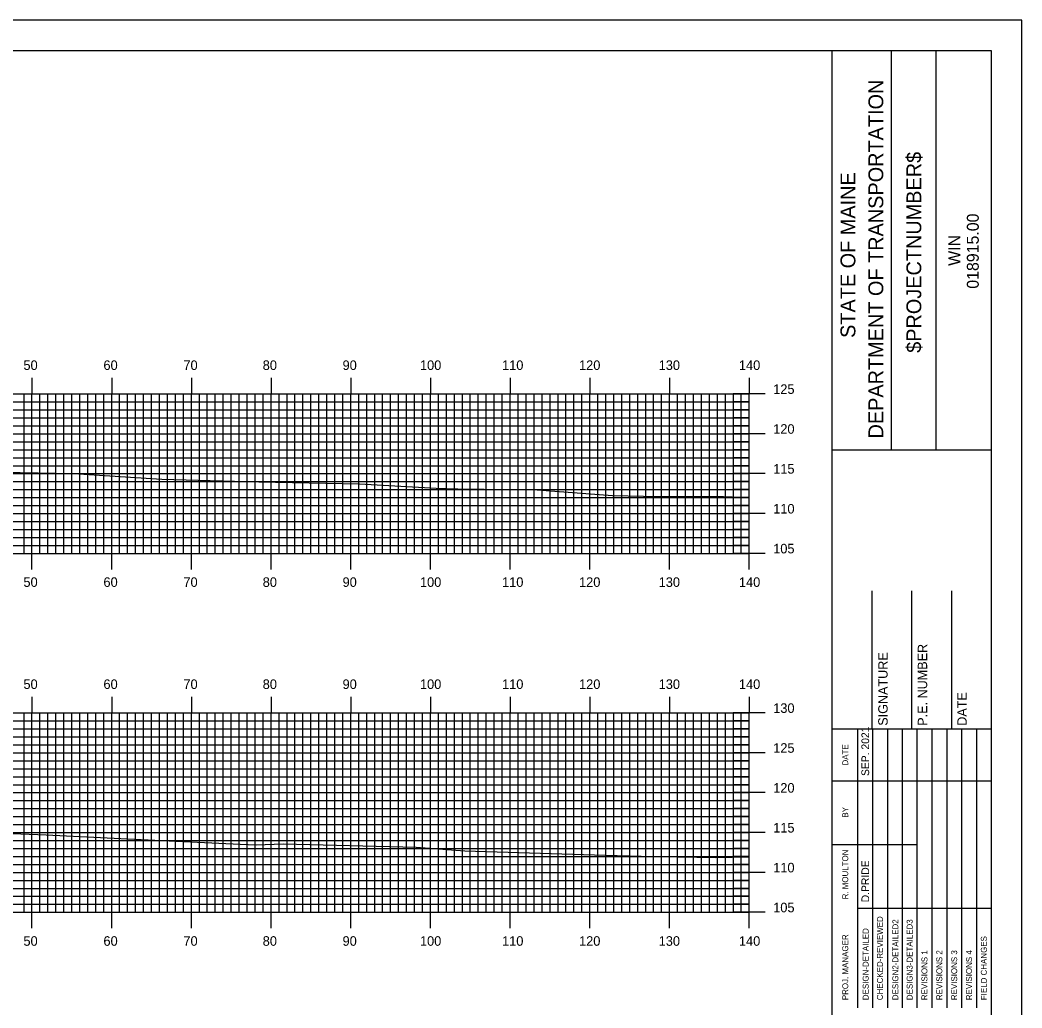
# Model space of a CAD drawing. Extents: x 1780286 to 1780629, y 442591 to 442811.
# Drawn here: x 1780500.4 to 1780626.1, y 442686.7 to 442810.5 of the extents above; entities that cross this region are included whole.
import ezdxf

# ---------------------------------------------------------------- set-up
doc = ezdxf.new("R2010")
doc.units = 0
for name, color, linetype in [('BORDER', 7, 'Continuous'), ('H_V ANNOTATION', 7, 'Continuous'), ('MAJOR', 7, 'Continuous'), ('MINOR', 7, 'Continuous'), ('PLOT BOUNDARY', 7, 'Continuous'), ('S_Roadway_Centerline', 7, 'Continuous')]:
    doc.layers.add(name, color=color, linetype=linetype)

msp = doc.modelspace()

# ---------------------------------------------------------------- linework, layer by layer
at = {"layer": 'BORDER'}
for p, q in [((1780602.27, 442596.67), (1780602.27, 442806.67)), ((1780609.73, 442756.66), (1780609.73, 442806.66)), ((1780615.32, 442756.66), (1780615.32, 442806.66)), ((1780602.27, 442756.65), (1780622.27, 442756.65)), ((1780607.27, 442721.67), (1780607.27, 442738.97)), ((1780612.27, 442721.67), (1780612.27, 442738.97)), ((1780617.27, 442721.67), (1780617.27, 442738.97)), ((1780602.27, 442721.67), (1780622.27, 442721.67))]:
    msp.add_line(p, q, dxfattribs=at)
msp.add_lwpolyline([(1780302.27, 442596.67), (1780622.27, 442596.67), (1780622.27, 442806.67), (1780302.27, 442806.67)], close=True, dxfattribs=at)
for points in [[(1780605.5, 442715.17), (1780605.5, 442721.67)], [(1780607.36, 442686.68), (1780607.36, 442721.67)], [(1780609.23, 442721.67), (1780609.23, 442686.68)], [(1780611.09, 442686.68), (1780611.09, 442721.67)], [(1780612.95, 442686.68), (1780612.95, 442721.67)], [(1780614.82, 442686.68), (1780614.82, 442721.67)], [(1780616.68, 442686.68), (1780616.68, 442721.67)], [(1780618.54, 442686.68), (1780618.54, 442721.67)], [(1780620.41, 442686.68), (1780620.41, 442721.67)], [(1780605.5, 442686.68), (1780605.5, 442720.26)], [(1780602.27, 442715.17), (1780622.27, 442715.17)], [(1780602.27, 442707.17), (1780605.5, 442707.17)], [(1780605.5, 442707.17), (1780612.95, 442707.17)], [(1780605.5, 442699.17), (1780622.27, 442699.17)]]:
    msp.add_lwpolyline(points, dxfattribs=at)
at = {"layer": 'MAJOR'}
for p, q in [((1780501.87, 442765.67), (1780501.87, 442763.67)), ((1780511.87, 442765.67), (1780511.87, 442763.67)), ((1780521.87, 442765.67), (1780521.87, 442763.67)), ((1780531.87, 442765.67), (1780531.87, 442763.67)), ((1780541.87, 442765.67), (1780541.87, 442763.67)), ((1780551.87, 442765.67), (1780551.87, 442763.67)), ((1780561.87, 442765.67), (1780561.87, 442763.67)), ((1780571.87, 442765.67), (1780571.87, 442763.67)), ((1780581.87, 442765.67), (1780581.87, 442763.67)), ((1780591.87, 442765.67), (1780591.87, 442763.67)), ((1780311.87, 442763.67), (1780591.87, 442763.67)), ((1780311.87, 442763.67), (1780591.87, 442763.67)), ((1780501.87, 442743.67), (1780501.87, 442763.67)), ((1780511.87, 442743.67), (1780511.87, 442763.67)), ((1780521.87, 442743.67), (1780521.87, 442763.67)), ((1780531.87, 442743.67), (1780531.87, 442763.67)), ((1780541.87, 442743.67), (1780541.87, 442763.67)), ((1780551.87, 442743.67), (1780551.87, 442763.67)), ((1780561.87, 442743.67), (1780561.87, 442763.67)), ((1780571.87, 442743.67), (1780571.87, 442763.67)), ((1780581.87, 442743.67), (1780581.87, 442763.67)), ((1780593.87, 442763.67), (1780589.86, 442763.67)), ((1780591.87, 442743.67), (1780591.87, 442763.67)), ((1780591.87, 442743.67), (1780591.87, 442763.67)), ((1780311.87, 442758.67), (1780591.87, 442758.67)), ((1780593.87, 442758.67), (1780589.86, 442758.67)), ((1780311.87, 442753.67), (1780591.87, 442753.67)), ((1780593.87, 442753.67), (1780589.86, 442753.67)), ((1780311.87, 442748.67), (1780591.87, 442748.67)), ((1780593.87, 442748.67), (1780589.86, 442748.67)), ((1780311.87, 442743.67), (1780591.87, 442743.67)), ((1780311.87, 442743.67), (1780591.87, 442743.67)), ((1780501.87, 442741.66), (1780501.87, 442743.67)), ((1780511.87, 442741.66), (1780511.87, 442743.67)), ((1780521.87, 442741.66), (1780521.87, 442743.67)), ((1780531.87, 442741.66), (1780531.87, 442743.67)), ((1780541.87, 442741.66), (1780541.87, 442743.67)), ((1780551.87, 442741.66), (1780551.87, 442743.67)), ((1780561.87, 442741.66), (1780561.87, 442743.67)), ((1780571.87, 442741.66), (1780571.87, 442743.67)), ((1780581.87, 442741.66), (1780581.87, 442743.67)), ((1780593.87, 442743.67), (1780589.86, 442743.67)), ((1780591.87, 442741.66), (1780591.87, 442743.67)), ((1780501.87, 442725.67), (1780501.87, 442723.67)), ((1780511.87, 442725.67), (1780511.87, 442723.67)), ((1780521.87, 442725.67), (1780521.87, 442723.67)), ((1780531.87, 442725.67), (1780531.87, 442723.67)), ((1780541.87, 442725.67), (1780541.87, 442723.67)), ((1780551.87, 442725.67), (1780551.87, 442723.67)), ((1780561.87, 442725.67), (1780561.87, 442723.67)), ((1780571.87, 442725.67), (1780571.87, 442723.67)), ((1780581.87, 442725.67), (1780581.87, 442723.67)), ((1780591.87, 442725.67), (1780591.87, 442723.67)), ((1780311.87, 442723.67), (1780591.87, 442723.67)), ((1780311.87, 442723.67), (1780591.87, 442723.67)), ((1780501.87, 442698.67), (1780501.87, 442723.67)), ((1780511.87, 442698.67), (1780511.87, 442723.67)), ((1780521.87, 442698.67), (1780521.87, 442723.67)), ((1780531.87, 442698.67), (1780531.87, 442723.67)), ((1780541.87, 442698.67), (1780541.87, 442723.67)), ((1780551.87, 442698.67), (1780551.87, 442723.67)), ((1780561.87, 442698.67), (1780561.87, 442723.67)), ((1780571.87, 442698.67), (1780571.87, 442723.67)), ((1780581.87, 442698.67), (1780581.87, 442723.67)), ((1780593.87, 442723.67), (1780589.86, 442723.67)), ((1780591.87, 442698.67), (1780591.87, 442723.67)), ((1780591.87, 442698.67), (1780591.87, 442723.67)), ((1780311.87, 442718.67), (1780591.87, 442718.67)), ((1780593.87, 442718.67), (1780589.86, 442718.67)), ((1780311.87, 442713.67), (1780591.87, 442713.67)), ((1780593.87, 442713.67), (1780589.86, 442713.67)), ((1780311.87, 442708.67), (1780591.87, 442708.67)), ((1780593.87, 442708.67), (1780589.86, 442708.67)), ((1780311.87, 442703.67), (1780591.87, 442703.67)), ((1780593.87, 442703.67), (1780589.86, 442703.67)), ((1780311.87, 442698.67), (1780591.87, 442698.67)), ((1780311.87, 442698.67), (1780591.87, 442698.67)), ((1780501.87, 442696.66), (1780501.87, 442698.67)), ((1780511.87, 442696.66), (1780511.87, 442698.67)), ((1780521.87, 442696.66), (1780521.87, 442698.67)), ((1780531.87, 442696.66), (1780531.87, 442698.67)), ((1780541.87, 442696.66), (1780541.87, 442698.67)), ((1780551.87, 442696.66), (1780551.87, 442698.67)), ((1780561.87, 442696.66), (1780561.87, 442698.67)), ((1780571.87, 442696.66), (1780571.87, 442698.67)), ((1780581.87, 442696.66), (1780581.87, 442698.67)), ((1780593.87, 442698.67), (1780589.86, 442698.67)), ((1780591.87, 442696.66), (1780591.87, 442698.67))]:
    msp.add_line(p, q, dxfattribs=at)
at = {"layer": 'MINOR'}
for p, q in [((1780500.87, 442743.67), (1780500.87, 442763.67)), ((1780502.87, 442743.67), (1780502.87, 442763.67)), ((1780503.87, 442743.67), (1780503.87, 442763.67)), ((1780504.87, 442743.67), (1780504.87, 442763.67)), ((1780505.87, 442743.67), (1780505.87, 442763.67)), ((1780506.87, 442743.67), (1780506.87, 442763.67)), ((1780507.87, 442743.67), (1780507.87, 442763.67)), ((1780508.87, 442743.67), (1780508.87, 442763.67)), ((1780509.87, 442743.67), (1780509.87, 442763.67)), ((1780510.87, 442743.67), (1780510.87, 442763.67)), ((1780512.87, 442743.67), (1780512.87, 442763.67)), ((1780513.87, 442743.67), (1780513.87, 442763.67)), ((1780514.87, 442743.67), (1780514.87, 442763.67)), ((1780515.87, 442743.67), (1780515.87, 442763.67)), ((1780516.87, 442743.67), (1780516.87, 442763.67)), ((1780517.87, 442743.67), (1780517.87, 442763.67)), ((1780518.87, 442743.67), (1780518.87, 442763.67)), ((1780519.87, 442743.67), (1780519.87, 442763.67)), ((1780520.87, 442743.67), (1780520.87, 442763.67)), ((1780522.87, 442743.67), (1780522.87, 442763.67)), ((1780523.87, 442743.67), (1780523.87, 442763.67)), ((1780524.87, 442743.67), (1780524.87, 442763.67)), ((1780525.87, 442743.67), (1780525.87, 442763.67)), ((1780526.87, 442743.67), (1780526.87, 442763.67)), ((1780527.87, 442743.67), (1780527.87, 442763.67)), ((1780528.87, 442743.67), (1780528.87, 442763.67)), ((1780529.87, 442743.67), (1780529.87, 442763.67)), ((1780530.87, 442743.67), (1780530.87, 442763.67)), ((1780532.87, 442743.67), (1780532.87, 442763.67)), ((1780533.87, 442743.67), (1780533.87, 442763.67)), ((1780534.87, 442743.67), (1780534.87, 442763.67)), ((1780535.87, 442743.67), (1780535.87, 442763.67)), ((1780536.87, 442743.67), (1780536.87, 442763.67)), ((1780537.87, 442743.67), (1780537.87, 442763.67)), ((1780538.87, 442743.67), (1780538.87, 442763.67)), ((1780539.87, 442743.67), (1780539.87, 442763.67)), ((1780540.87, 442743.67), (1780540.87, 442763.67)), ((1780542.87, 442743.67), (1780542.87, 442763.67)), ((1780543.87, 442743.67), (1780543.87, 442763.67)), ((1780544.87, 442743.67), (1780544.87, 442763.67)), ((1780545.87, 442743.67), (1780545.87, 442763.67)), ((1780546.87, 442743.67), (1780546.87, 442763.67)), ((1780547.87, 442743.67), (1780547.87, 442763.67)), ((1780548.87, 442743.67), (1780548.87, 442763.67)), ((1780549.87, 442743.67), (1780549.87, 442763.67)), ((1780550.87, 442743.67), (1780550.87, 442763.67)), ((1780552.87, 442743.67), (1780552.87, 442763.67)), ((1780553.87, 442743.67), (1780553.87, 442763.67)), ((1780554.87, 442743.67), (1780554.87, 442763.67)), ((1780555.87, 442743.67), (1780555.87, 442763.67)), ((1780556.87, 442743.67), (1780556.87, 442763.67)), ((1780557.87, 442743.67), (1780557.87, 442763.67)), ((1780558.87, 442743.67), (1780558.87, 442763.67)), ((1780559.87, 442743.67), (1780559.87, 442763.67)), ((1780560.87, 442743.67), (1780560.87, 442763.67)), ((1780562.87, 442743.67), (1780562.87, 442763.67)), ((1780563.87, 442743.67), (1780563.87, 442763.67)), ((1780564.87, 442743.67), (1780564.87, 442763.67)), ((1780565.87, 442743.67), (1780565.87, 442763.67)), ((1780566.87, 442743.67), (1780566.87, 442763.67)), ((1780567.87, 442743.67), (1780567.87, 442763.67)), ((1780568.87, 442743.67), (1780568.87, 442763.67)), ((1780569.87, 442743.67), (1780569.87, 442763.67)), ((1780570.87, 442743.67), (1780570.87, 442763.67)), ((1780572.87, 442743.67), (1780572.87, 442763.67)), ((1780573.87, 442743.67), (1780573.87, 442763.67)), ((1780574.87, 442743.67), (1780574.87, 442763.67)), ((1780575.87, 442743.67), (1780575.87, 442763.67)), ((1780576.87, 442743.67), (1780576.87, 442763.67)), ((1780577.87, 442743.67), (1780577.87, 442763.67)), ((1780578.87, 442743.67), (1780578.87, 442763.67)), ((1780579.87, 442743.67), (1780579.87, 442763.67)), ((1780580.87, 442743.67), (1780580.87, 442763.67)), ((1780582.87, 442743.67), (1780582.87, 442763.67)), ((1780583.87, 442743.67), (1780583.87, 442763.67)), ((1780584.87, 442743.67), (1780584.87, 442763.67)), ((1780585.87, 442743.67), (1780585.87, 442763.67)), ((1780586.87, 442743.67), (1780586.87, 442763.67)), ((1780587.87, 442743.67), (1780587.87, 442763.67)), ((1780588.87, 442743.67), (1780588.87, 442763.67)), ((1780589.87, 442743.67), (1780589.87, 442763.67)), ((1780590.87, 442743.67), (1780590.87, 442763.67)), ((1780311.87, 442762.67), (1780591.87, 442762.67)), ((1780311.87, 442761.67), (1780591.87, 442761.67)), ((1780591.87, 442762.67), (1780589.86, 442762.67)), ((1780591.87, 442761.67), (1780589.86, 442761.67)), ((1780311.87, 442760.67), (1780591.87, 442760.67)), ((1780591.87, 442760.67), (1780589.86, 442760.67)), ((1780311.87, 442759.67), (1780591.87, 442759.67)), ((1780591.87, 442759.67), (1780589.86, 442759.67)), ((1780311.87, 442757.67), (1780591.87, 442757.67)), ((1780311.87, 442756.67), (1780591.87, 442756.67)), ((1780591.87, 442757.67), (1780589.86, 442757.67)), ((1780591.87, 442756.67), (1780589.86, 442756.67)), ((1780311.87, 442755.67), (1780591.87, 442755.67)), ((1780591.87, 442755.67), (1780589.86, 442755.67)), ((1780311.87, 442754.67), (1780591.87, 442754.67)), ((1780591.87, 442754.67), (1780589.86, 442754.67)), ((1780311.87, 442752.67), (1780591.87, 442752.67)), ((1780591.87, 442752.67), (1780589.86, 442752.67)), ((1780311.87, 442751.67), (1780591.87, 442751.67)), ((1780591.87, 442751.67), (1780589.86, 442751.67)), ((1780311.87, 442750.67), (1780591.87, 442750.67)), ((1780591.87, 442750.67), (1780589.86, 442750.67)), ((1780311.87, 442749.67), (1780591.87, 442749.67)), ((1780591.87, 442749.67), (1780589.86, 442749.67)), ((1780311.87, 442747.67), (1780591.87, 442747.67)), ((1780591.87, 442747.67), (1780589.86, 442747.67)), ((1780311.87, 442746.67), (1780591.87, 442746.67)), ((1780591.87, 442746.67), (1780589.86, 442746.67)), ((1780311.87, 442745.67), (1780591.87, 442745.67)), ((1780591.87, 442745.67), (1780589.86, 442745.67)), ((1780311.87, 442744.67), (1780591.87, 442744.67)), ((1780591.87, 442744.67), (1780589.86, 442744.67)), ((1780311.87, 442722.67), (1780591.87, 442722.67)), ((1780500.87, 442698.67), (1780500.87, 442723.67)), ((1780502.87, 442698.67), (1780502.87, 442723.67)), ((1780503.87, 442698.67), (1780503.87, 442723.67)), ((1780504.87, 442698.67), (1780504.87, 442723.67)), ((1780505.87, 442698.67), (1780505.87, 442723.67)), ((1780506.87, 442698.67), (1780506.87, 442723.67)), ((1780507.87, 442698.67), (1780507.87, 442723.67)), ((1780508.87, 442698.67), (1780508.87, 442723.67)), ((1780509.87, 442698.67), (1780509.87, 442723.67)), ((1780510.87, 442698.67), (1780510.87, 442723.67)), ((1780512.87, 442698.67), (1780512.87, 442723.67)), ((1780513.87, 442698.67), (1780513.87, 442723.67)), ((1780514.87, 442698.67), (1780514.87, 442723.67)), ((1780515.87, 442698.67), (1780515.87, 442723.67)), ((1780516.87, 442698.67), (1780516.87, 442723.67)), ((1780517.87, 442698.67), (1780517.87, 442723.67)), ((1780518.87, 442698.67), (1780518.87, 442723.67)), ((1780519.87, 442698.67), (1780519.87, 442723.67)), ((1780520.87, 442698.67), (1780520.87, 442723.67)), ((1780522.87, 442698.67), (1780522.87, 442723.67)), ((1780523.87, 442698.67), (1780523.87, 442723.67)), ((1780524.87, 442698.67), (1780524.87, 442723.67)), ((1780525.87, 442698.67), (1780525.87, 442723.67)), ((1780526.87, 442698.67), (1780526.87, 442723.67)), ((1780527.87, 442698.67), (1780527.87, 442723.67)), ((1780528.87, 442698.67), (1780528.87, 442723.67)), ((1780529.87, 442698.67), (1780529.87, 442723.67)), ((1780530.87, 442698.67), (1780530.87, 442723.67)), ((1780532.87, 442698.67), (1780532.87, 442723.67)), ((1780533.87, 442698.67), (1780533.87, 442723.67)), ((1780534.87, 442698.67), (1780534.87, 442723.67)), ((1780535.87, 442698.67), (1780535.87, 442723.67)), ((1780536.87, 442698.67), (1780536.87, 442723.67)), ((1780537.87, 442698.67), (1780537.87, 442723.67)), ((1780538.87, 442698.67), (1780538.87, 442723.67)), ((1780539.87, 442698.67), (1780539.87, 442723.67)), ((1780540.87, 442698.67), (1780540.87, 442723.67)), ((1780542.87, 442698.67), (1780542.87, 442723.67)), ((1780543.87, 442698.67), (1780543.87, 442723.67)), ((1780544.87, 442698.67), (1780544.87, 442723.67)), ((1780545.87, 442698.67), (1780545.87, 442723.67)), ((1780546.87, 442698.67), (1780546.87, 442723.67)), ((1780547.87, 442698.67), (1780547.87, 442723.67)), ((1780548.87, 442698.67), (1780548.87, 442723.67)), ((1780549.87, 442698.67), (1780549.87, 442723.67)), ((1780550.87, 442698.67), (1780550.87, 442723.67)), ((1780552.87, 442698.67), (1780552.87, 442723.67)), ((1780553.87, 442698.67), (1780553.87, 442723.67)), ((1780554.87, 442698.67), (1780554.87, 442723.67)), ((1780555.87, 442698.67), (1780555.87, 442723.67)), ((1780556.87, 442698.67), (1780556.87, 442723.67)), ((1780557.87, 442698.67), (1780557.87, 442723.67)), ((1780558.87, 442698.67), (1780558.87, 442723.67)), ((1780559.87, 442698.67), (1780559.87, 442723.67)), ((1780560.87, 442698.67), (1780560.87, 442723.67)), ((1780562.87, 442698.67), (1780562.87, 442723.67)), ((1780563.87, 442698.67), (1780563.87, 442723.67)), ((1780564.87, 442698.67), (1780564.87, 442723.67)), ((1780565.87, 442698.67), (1780565.87, 442723.67)), ((1780566.87, 442698.67), (1780566.87, 442723.67)), ((1780567.87, 442698.67), (1780567.87, 442723.67)), ((1780568.87, 442698.67), (1780568.87, 442723.67)), ((1780569.87, 442698.67), (1780569.87, 442723.67)), ((1780570.87, 442698.67), (1780570.87, 442723.67)), ((1780572.87, 442698.67), (1780572.87, 442723.67)), ((1780573.87, 442698.67), (1780573.87, 442723.67)), ((1780574.87, 442698.67), (1780574.87, 442723.67)), ((1780575.87, 442698.67), (1780575.87, 442723.67)), ((1780576.87, 442698.67), (1780576.87, 442723.67)), ((1780577.87, 442698.67), (1780577.87, 442723.67)), ((1780578.87, 442698.67), (1780578.87, 442723.67)), ((1780579.87, 442698.67), (1780579.87, 442723.67)), ((1780580.87, 442698.67), (1780580.87, 442723.67)), ((1780582.87, 442698.67), (1780582.87, 442723.67)), ((1780583.87, 442698.67), (1780583.87, 442723.67)), ((1780584.87, 442698.67), (1780584.87, 442723.67)), ((1780585.87, 442698.67), (1780585.87, 442723.67)), ((1780586.87, 442698.67), (1780586.87, 442723.67)), ((1780587.87, 442698.67), (1780587.87, 442723.67)), ((1780588.87, 442698.67), (1780588.87, 442723.67)), ((1780591.87, 442722.67), (1780589.86, 442722.67)), ((1780589.87, 442698.67), (1780589.87, 442723.67)), ((1780590.87, 442698.67), (1780590.87, 442723.67)), ((1780311.87, 442721.67), (1780591.87, 442721.67)), ((1780591.87, 442721.67), (1780589.86, 442721.67)), ((1780311.87, 442720.67), (1780591.87, 442720.67)), ((1780591.87, 442720.67), (1780589.86, 442720.67)), ((1780311.87, 442719.67), (1780591.87, 442719.67)), ((1780591.87, 442719.67), (1780589.86, 442719.67)), ((1780311.87, 442717.67), (1780591.87, 442717.67)), ((1780591.87, 442717.67), (1780589.86, 442717.67)), ((1780311.87, 442716.67), (1780591.87, 442716.67)), ((1780591.87, 442716.67), (1780589.86, 442716.67)), ((1780311.87, 442715.67), (1780591.87, 442715.67)), ((1780591.87, 442715.67), (1780589.86, 442715.67)), ((1780311.87, 442714.67), (1780591.87, 442714.67)), ((1780591.87, 442714.67), (1780589.86, 442714.67)), ((1780311.87, 442712.67), (1780591.87, 442712.67)), ((1780591.87, 442712.67), (1780589.86, 442712.67)), ((1780311.87, 442711.67), (1780591.87, 442711.67)), ((1780591.87, 442711.67), (1780589.86, 442711.67)), ((1780311.87, 442710.67), (1780591.87, 442710.67)), ((1780591.87, 442710.67), (1780589.86, 442710.67)), ((1780311.87, 442709.67), (1780591.87, 442709.67)), ((1780591.87, 442709.67), (1780589.86, 442709.67)), ((1780311.87, 442707.67), (1780591.87, 442707.67)), ((1780591.87, 442707.67), (1780589.86, 442707.67)), ((1780311.87, 442706.67), (1780591.87, 442706.67)), ((1780591.87, 442706.67), (1780589.86, 442706.67)), ((1780311.87, 442705.67), (1780591.87, 442705.67)), ((1780591.87, 442705.67), (1780589.86, 442705.67)), ((1780311.87, 442704.67), (1780591.87, 442704.67)), ((1780591.87, 442704.67), (1780589.86, 442704.67)), ((1780311.87, 442702.67), (1780591.87, 442702.67)), ((1780591.87, 442702.67), (1780589.86, 442702.67)), ((1780311.87, 442701.67), (1780591.87, 442701.67)), ((1780591.87, 442701.67), (1780589.86, 442701.67)), ((1780311.87, 442700.67), (1780591.87, 442700.67)), ((1780591.87, 442700.67), (1780589.86, 442700.67)), ((1780311.87, 442699.67), (1780591.87, 442699.67)), ((1780591.87, 442699.67), (1780589.86, 442699.67))]:
    msp.add_line(p, q, dxfattribs=at)
at = {"layer": 'PLOT BOUNDARY'}
msp.add_lwpolyline([(1780286.08, 442590.55), (1780626.08, 442590.55), (1780626.08, 442810.55), (1780286.08, 442810.55)], close=True, dxfattribs=at)
at = {"layer": 'S_Roadway_Centerline'}
for points in [[(1780495.91, 442753.89), (1780507.1, 442753.7), (1780508.39, 442753.62), (1780518.16, 442752.98), (1780530.34, 442752.65), (1780542.97, 442752.4), (1780552.6, 442751.87), (1780555.31, 442751.75), (1780565.26, 442751.64), (1780574.69, 442750.93), (1780578.6, 442750.86), (1780588.62, 442750.82), (1780591.87, 442750.69)], [(1780494.02, 442708.76), (1780503.64, 442708.4), (1780517.3, 442707.72), (1780528, 442707.19), (1780529.99, 442707.12), (1780533.37, 442707.25), (1780550.06, 442706.83), (1780556.16, 442706.37), (1780573.78, 442705.83), (1780578.29, 442705.71), (1780587.57, 442705.52), (1780591.87, 442705.62)]]:
    msp.add_lwpolyline(points, dxfattribs=at)

# ---------------------------------------------------------------- texts
at = {"layer": 'BORDER'}
for s, height, p in [('DEPARTMENT OF TRANSPORTATION', 1.8635, (1780608.68, 442758.08)), ('$PROJECTNUMBER$', 1.8635, (1780613.45, 442768.82)), ('STATE OF MAINE', 1.8635, (1780605.18, 442770.69)), ('018915.00', 1.491, (1780620.66, 442776.86)), ('WIN', 1.491, (1780618.34, 442779.73)), ('P.E. NUMBER', 1.1811, (1780614.19, 442722.06)), ('SIGNATURE', 1.181, (1780609.23, 442722.06)), ('DATE', 1.181, (1780619.15, 442722.06)), ('SEP. 2021', 0.969, (1780606.91, 442715.76)), ('DATE', 0.743, (1780604.28, 442717.08)), ('BY', 0.743, (1780604.28, 442710.54)), ('R. MOULTON', 0.745, (1780604.28, 442700.28)), ('D.PRIDE', 0.969, (1780606.91, 442699.92)), ('CHECKED-REVIEWED', 0.7455, (1780608.63, 442687.65)), ('DESIGN2-DETAILED2', 0.7455, (1780610.57, 442687.65)), ('DESIGN3-DETAILED3', 0.7455, (1780612.36, 442687.65)), ('DESIGN-DETAILED', 0.7455, (1780606.84, 442687.65)), ('PROJ. MANAGER', 0.7455, (1780604.28, 442687.65)), ('FIELD CHANGES', 0.7455, (1780621.67, 442687.65)), ('REVISIONS 1', 0.7455, (1780614.22, 442687.65)), ('REVISIONS 2', 0.7455, (1780616.08, 442687.65)), ('REVISIONS 3', 0.7455, (1780617.95, 442687.65)), ('REVISIONS 4', 0.7455, (1780619.81, 442687.65))]:
    msp.add_text(s, height=height, rotation=90, dxfattribs=at).set_placement(p)
at = {"layer": 'H_V ANNOTATION'}
for s, p in [('50', (1780500.8, 442766.67)), ('60', (1780510.84, 442766.67)), ('70', (1780520.87, 442766.67)), ('80', (1780530.82, 442766.67)), ('90', (1780540.84, 442766.67)), ('100', (1780550.55, 442766.67)), ('110', (1780560.85, 442766.67)), ('120', (1780570.51, 442766.67)), ('130', (1780580.5, 442766.67)), ('140', (1780590.57, 442766.67)), ('125', (1780594.87, 442763.67)), ('120', (1780594.87, 442758.67)), ('115', (1780594.87, 442753.67)), ('110', (1780594.87, 442748.67)), ('105', (1780594.87, 442743.67)), ('50', (1780500.8, 442739.47)), ('60', (1780510.84, 442739.47)), ('70', (1780520.87, 442739.47)), ('80', (1780530.82, 442739.47)), ('90', (1780540.84, 442739.47)), ('100', (1780550.55, 442739.47)), ('110', (1780560.85, 442739.47)), ('120', (1780570.51, 442739.47)), ('130', (1780580.5, 442739.47)), ('140', (1780590.57, 442739.47)), ('50', (1780500.8, 442726.67)), ('60', (1780510.84, 442726.67)), ('70', (1780520.87, 442726.67)), ('80', (1780530.82, 442726.67)), ('90', (1780540.84, 442726.67)), ('100', (1780550.55, 442726.67)), ('110', (1780560.85, 442726.67)), ('120', (1780570.51, 442726.67)), ('130', (1780580.5, 442726.67)), ('140', (1780590.57, 442726.67)), ('130', (1780594.87, 442723.67)), ('125', (1780594.87, 442718.67)), ('120', (1780594.87, 442713.67)), ('115', (1780594.87, 442708.67)), ('110', (1780594.87, 442703.67)), ('105', (1780594.87, 442698.67)), ('50', (1780500.8, 442694.47)), ('60', (1780510.84, 442694.47)), ('70', (1780520.87, 442694.47)), ('80', (1780530.82, 442694.47)), ('90', (1780540.84, 442694.47)), ('100', (1780550.55, 442694.47)), ('110', (1780560.85, 442694.47)), ('120', (1780570.51, 442694.47)), ('130', (1780580.5, 442694.47)), ('140', (1780590.57, 442694.47))]:
    msp.add_text(s, height=1.2, dxfattribs=at).set_placement(p)

doc.saveas('drawing.dxf')
